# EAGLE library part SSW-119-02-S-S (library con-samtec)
THROUGH-HOLE .025" SQ POST SOCKET Source: Samtec SSW.pdf
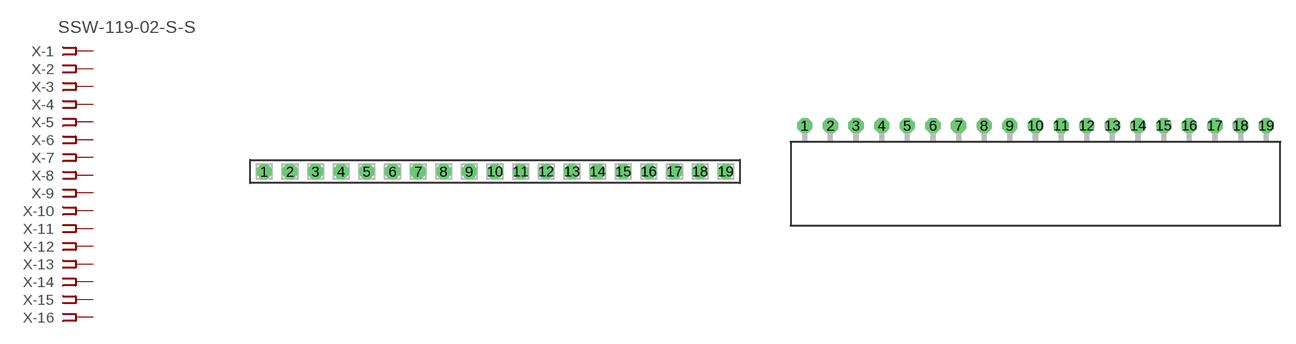
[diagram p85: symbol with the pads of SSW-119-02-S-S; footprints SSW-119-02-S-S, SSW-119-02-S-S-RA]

Designator prefix X; gates -1=FPINV -2=FPIN -3=FPIN -4=FPIN -5=FPIN -6=FPIN -7=FPIN -8=FPIN -9=FPIN -10=FPIN -11=FPIN -12=FPIN -13=FPIN -14=FPIN -15=FPIN -16=FPIN -17=FPIN -18=FPIN -19=FPIN

## SSW-119-02-S-S (MPN: SSW-119-02-S-S; OC_FARNELL: unknown; OC_NEWARK: 11P9625)  [SSW-119-02-S-S]
1  -1:1  pas
2  -2:1  pas
3  -3:1  pas
4  -4:1  pas
5  -5:1  pas
6  -6:1  pas
7  -7:1  pas
8  -8:1  pas
9  -9:1  pas
10  -10:1  pas
11  -11:1  pas
12  -12:1  pas
13  -13:1  pas
14  -14:1  pas
15  -15:1  pas
16  -16:1  pas
17  -17:1  pas
18  -18:1  pas
19  -19:1  pas

## SSW-119-02-S-S-RA (MPN: SSW-119-02-S-S-RA; OC_FARNELL: unknown; OC_NEWARK: 11P9626)  [SSW-119-02-S-S-RA]
Pads as for SSW-119-02-S-S

## Footprint SSW-119-02-S-S (pad centres in mm)
THROUGH-HOLE .025" SQ POST SOCKET Source: Samtec SSW.pdf
drill 1 pad 1.5 octagon: 1 -22.86,0; 2 -20.32,0; 3 -17.78,0; 4 -15.24,0; 5 -12.7,0; 6 -10.16,0; 7 -7.62,0; 8 -5.08,0; 9 -2.54,0; 10 0,0; 11 2.54,0; 12 5.08,0; 13 7.62,0; 14 10.16,0; 15 12.7,0; 16 15.24,0; 17 17.78,0; 18 20.32,0; 19 22.86,0

## Footprint SSW-119-02-S-S-RA (pad centres in mm)
THROUGH-HOLE .025" SQ POST SOCKET Source: Samtec SSW.pdf
drill 1 pad 1.5 octagon: 1 -22.86,1.524; 2 -20.32,1.524; 3 -17.78,1.524; 4 -15.24,1.524; 5 -12.7,1.524; 6 -10.16,1.524; 7 -7.62,1.524; 8 -5.08,1.524; 9 -2.54,1.524; 10 0,1.524; 11 2.54,1.524; 12 5.08,1.524; 13 7.62,1.524; 14 10.16,1.524; 15 12.7,1.524; 16 15.24,1.524; 17 17.78,1.524; 18 20.32,1.524; 19 22.86,1.524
